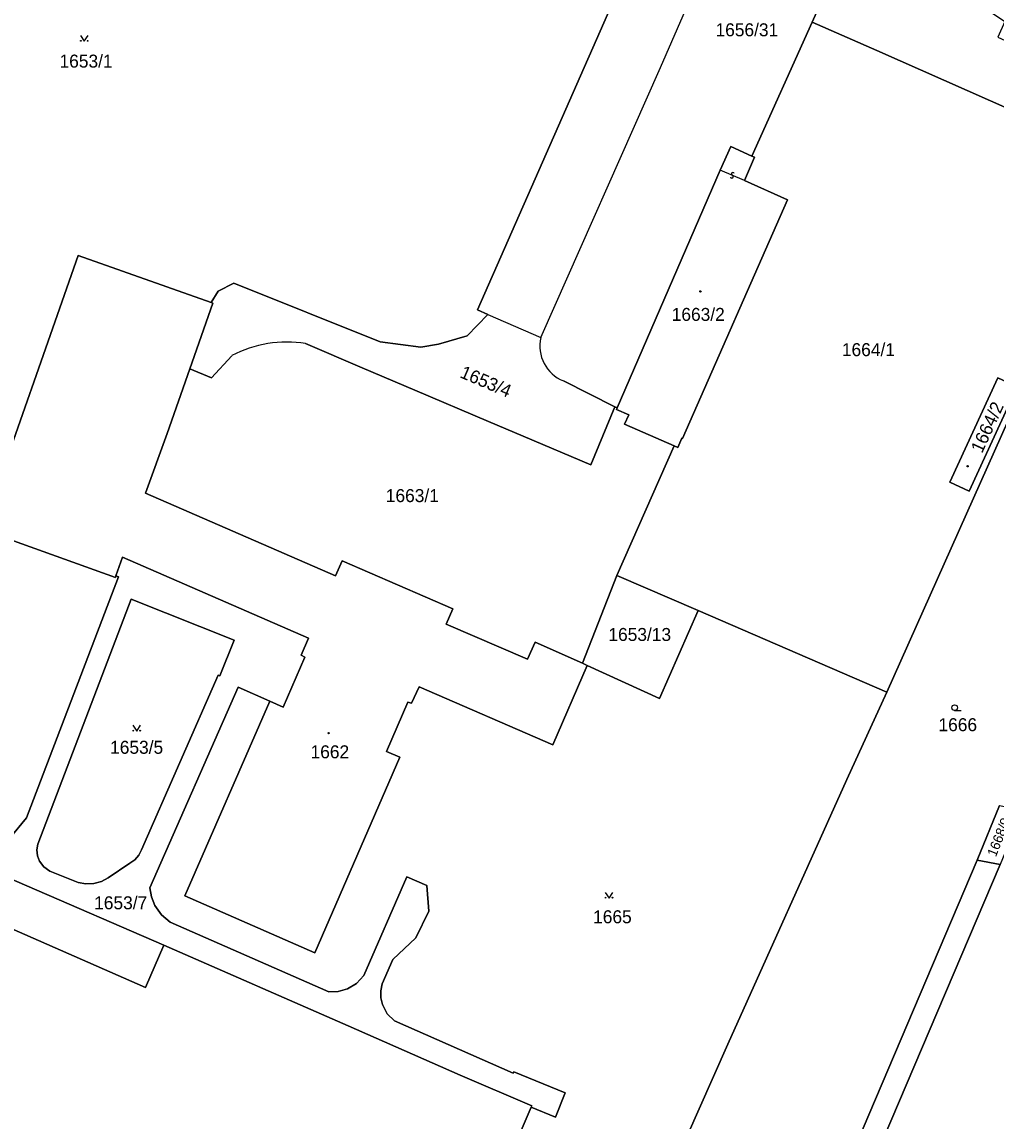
# Model space of a CAD drawing. Extents: x -596024 to -594475, y -1163820 to -1161957.
# Drawn here: x -595823.2 to -595695.5, y -1162318.6 to -1162174.7 of the extents above; entities that cross this region are included whole.
import ezdxf

# ---------------------------------------------------------------- set-up
doc = ezdxf.new("R2010")
doc.units = 0
for name, color, linetype in [('Level 1', 7, 'Continuous'), ('Level 13', 7, 'Continuous'), ('Level 3', 7, 'Continuous'), ('Level 4', 7, 'Continuous'), ('Level 5', 7, 'Continuous'), ('Level 60', 7, 'Continuous'), ('Vrstva 60', 7, 'Continuous')]:
    doc.layers.add(name, color=color, linetype=linetype)

msp = doc.modelspace()

# ---------------------------------------------------------------- linework, layer by layer
at = {"layer": 'Level 1'}
for points in [[(-595762.1, -1162212.98), (-595763.48, -1162212.38), (-595714.28, -1162100.65)], [(-595755.16, -1162216.01), (-595739.48, -1162180.64), (-595719.28, -1162134.23)], [(-595706, -1162144.24), (-595719.62, -1162174.71)], [(-595727.53, -1162192.23), (-595719.62, -1162174.71)], [(-595719.62, -1162174.71), (-595711.16, -1162178.38), (-595678.68, -1162192.78)], [(-595731.66, -1162194.09), (-595730.28, -1162190.99), (-595727.53, -1162192.23)], [(-595728.5, -1162195.42), (-595727.18, -1162192.39), (-595727.53, -1162192.23)], [(-595678.68, -1162192.78), (-595709.83, -1162262.45)], [(-595731.66, -1162194.09), (-595745.18, -1162225.22)], [(-595737.72, -1162230.18), (-595737.2, -1162230.4), (-595736.68, -1162229.18), (-595736.59, -1162229.22), (-595722.85, -1162197.97), (-595728.5, -1162195.42)], [(-595798.39, -1162211.43), (-595815.82, -1162205.27), (-595828.32, -1162240.78)], [(-595762.1, -1162212.98), (-595764.81, -1162215.77), (-595768.57, -1162216.89), (-595770.91, -1162217.26), (-595776.23, -1162216.55), (-595795.42, -1162208.87), (-595797.46, -1162209.91), (-595798.39, -1162211.43)], [(-595798.39, -1162211.43), (-595798.14, -1162211.52), (-595801.17, -1162220.09)], [(-595762.1, -1162212.98), (-595755.16, -1162216.01)], [(-595745.46, -1162225.1), (-595748.64, -1162232.68), (-595757.5, -1162228.92), (-595762.05, -1162226.98), (-595771.67, -1162222.89), (-595778.59, -1162219.96), (-595786, -1162216.78)], [(-595801.17, -1162220.09), (-595798.33, -1162221.3), (-595795.68, -1162218.38)], [(-595801.17, -1162220.09), (-595804.16, -1162228.57), (-595806.98, -1162236.41), (-595795.54, -1162241.38), (-595782.07, -1162247.23), (-595781.19, -1162245.24), (-595766.71, -1162251.52), (-595767.57, -1162253.56), (-595756.9, -1162258.12), (-595755.93, -1162255.92), (-595749.73, -1162258.67)], [(-595745.46, -1162225.1), (-595752.22, -1162221.68)], [(-595699.06, -1162236.11), (-595701.56, -1162234.96), (-595695.28, -1162221.28), (-595692.76, -1162222.44), (-595699.06, -1162236.11)], [(-595745.46, -1162225.1), (-595745.18, -1162225.22)], [(-595745.18, -1162225.22), (-595745.27, -1162225.42), (-595743.65, -1162226.13), (-595744.2, -1162227.37), (-595737.72, -1162230.18)], [(-595737.72, -1162230.18), (-595745.21, -1162247.19)], [(-595810.87, -1162247.24), (-595810.93, -1162247.42), (-595827.12, -1162241.64), (-595828.45, -1162241.16), (-595828.32, -1162240.78)], [(-595790.69, -1162263.65), (-595788.93, -1162264.41), (-595786.12, -1162257.87), (-595786.59, -1162257.63), (-595785.64, -1162255.37), (-595809.99, -1162244.79), (-595810.87, -1162247.24)], [(-595810.87, -1162247.24), (-595810.54, -1162247.36), (-595822.56, -1162278.91), (-595824.79, -1162281.63), (-595825.42, -1162282.16), (-595826.18, -1162282.47), (-595826.9, -1162282.53), (-595827.6, -1162282.39), (-595839.05, -1162277.47), (-595848.14, -1162273.48)], [(-595749.73, -1162258.67), (-595745.21, -1162247.19)], [(-595734.57, -1162251.78), (-595745.21, -1162247.19)], [(-595797.22, -1162260.3), (-595797.46, -1162260.23), (-595807.51, -1162283.11), (-595807.87, -1162283.81), (-595808.38, -1162284.41), (-595809.02, -1162284.87), (-595811.86, -1162286.77), (-595812.76, -1162287.25), (-595813.75, -1162287.52), (-595814.79, -1162287.57), (-595815.82, -1162287.38), (-595819.51, -1162285.89), (-595820.31, -1162285.36), (-595820.89, -1162284.6), (-595821.15, -1162283.89), (-595821.21, -1162283.13), (-595821.08, -1162282.39), (-595808.85, -1162250.28), (-595795.37, -1162255.65), (-595797.22, -1162260.3)], [(-595749.08, -1162258.96), (-595739.6, -1162263.29), (-595734.57, -1162251.78)], [(-595709.83, -1162262.45), (-595734.57, -1162251.78)], [(-595749.08, -1162258.96), (-595753.61, -1162269.36), (-595771.13, -1162261.77), (-595772.12, -1162263.92), (-595772.62, -1162263.76), (-595775.4, -1162270.23), (-595773.63, -1162270.99), (-595784.78, -1162296.59), (-595801.82, -1162289.13), (-595790.69, -1162263.65)], [(-595749.73, -1162258.67), (-595749.08, -1162258.96)], [(-595709.83, -1162262.45), (-595715.05, -1162273.88), (-595730.67, -1162308.59), (-595750.8, -1162353.99), (-595754.29, -1162361.8), (-595797.24, -1162364.8), (-595847.77, -1162368.33)], [(-595756.42, -1162316.82), (-595753.25, -1162318.13), (-595751.97, -1162314.94), (-595758.7, -1162312.19), (-595758.78, -1162312.38), (-595774.35, -1162305.52), (-595775.31, -1162304.58), (-595775.94, -1162303.39), (-595776.15, -1162302.5), (-595776.16, -1162301.58), (-595775.98, -1162300.68), (-595774.56, -1162297.47), (-595771.57, -1162294.66), (-595769.86, -1162291.13), (-595770.13, -1162287.77), (-595772.72, -1162286.67), (-595778.39, -1162299.57), (-595779.33, -1162300.61), (-595780.53, -1162301.34), (-595781.72, -1162301.68), (-595782.96, -1162301.72), (-595803.74, -1162292.6), (-595804.89, -1162291.64), (-595805.75, -1162290.41), (-595806.2, -1162289.28), (-595806.4, -1162288.08), (-595794.86, -1162261.82), (-595790.69, -1162263.65)], [(-595804.6, -1162295.61), (-595840.55, -1162280.07), (-595849.35, -1162276.28)], [(-595695.06, -1162277.29), (-595697.99, -1162284.45)], [(-595697.99, -1162284.45), (-595742.07, -1162388.02)], [(-595742.07, -1162388.02), (-595738.95, -1162388.28), (-595694.97, -1162285.05)], [(-595694.97, -1162285.05), (-595697.99, -1162284.45)], [(-595845.79, -1162320.43), (-595846.57, -1162317.95), (-595847.03, -1162315.39), (-595847.09, -1162313.01), (-595846.88, -1162310.63), (-595846.4, -1162308.3), (-595845.74, -1162306.24), (-595844.87, -1162304.26), (-595837.57, -1162287.72), (-595806.99, -1162301.14), (-595804.6, -1162295.61)], [(-595804.6, -1162295.61), (-595780.44, -1162306.15), (-595765.76, -1162312.62), (-595756.34, -1162316.64), (-595756.42, -1162316.82)], [(-595756.42, -1162316.82), (-595766.21, -1162339.62)]]:
    msp.add_lwpolyline(points, dxfattribs=at)
for centre, radius, start, end in [((-595750.42, -1162217.15), 4.87, 166.4752, 248.34), ((-595788.4, -1162232.32), 15.73, 81.2131, 117.558)]:
    msp.add_arc(centre, radius, start, end, dxfattribs=at)
at = {"layer": 'Level 13'}
for centre, start, end in [((-595730.15, -1162194.92), 194.5472, 66.6452), ((-595730.01, -1162194.58), 14.3327, 246.9227)]:
    msp.add_arc(centre, 0.184, start, end, dxfattribs=at)
at = {"layer": 'Level 3'}
msp.add_lwpolyline([(-595728.5, -1162195.42), (-595731.66, -1162194.09)], dxfattribs=at)
at = {"layer": 'Level 5'}
msp.add_line((-595700.94, -1162264.87), (-595700.07, -1162264.87), dxfattribs=at)
for points in [[(-595815.51, -1162176.44), (-595815.01, -1162177.19), (-595814.51, -1162176.44)], [(-595808.63, -1162266.8), (-595808.13, -1162267.55), (-595807.63, -1162266.8)], [(-595746.73, -1162288.68), (-595746.23, -1162289.43), (-595745.73, -1162288.68)]]:
    msp.add_lwpolyline(points, dxfattribs=at)
for centre, radius in [((-595815.46, -1162177.14), 0.05), ((-595814.56, -1162177.14), 0.05), ((-595734.26, -1162209.96), 0.09), ((-595734.26, -1162209.96), 0.0521), ((-595699.25, -1162232.86), 0.09), ((-595699.25, -1162232.86), 0.0521), ((-595700.94, -1162264.49), 0.375), ((-595808.58, -1162267.5), 0.05), ((-595807.68, -1162267.5), 0.05), ((-595782.98, -1162267.83), 0.09), ((-595782.98, -1162267.83), 0.0521), ((-595746.68, -1162289.38), 0.05), ((-595745.78, -1162289.38), 0.05)]:
    msp.add_circle(centre, radius, dxfattribs=at)
at = {"layer": 'Level 60'}
for points in [[(-595714.28, -1162100.65), (-595763.48, -1162212.38), (-595762.1, -1162212.98), (-595764.81, -1162215.77), (-595768.57, -1162216.89), (-595770.91, -1162217.26), (-595776.23, -1162216.55), (-595795.42, -1162208.87), (-595797.46, -1162209.91), (-595798.39, -1162211.43), (-595815.82, -1162205.27), (-595828.32, -1162240.78), (-595833.81, -1162238.93), (-595849.74, -1162233.3), (-595857.22, -1162230.69), (-595857.76, -1162222.73), (-595860.33, -1162182.22), (-595864.54, -1162120.48)], [(-595755.16, -1162216.01), (-595739.48, -1162180.64), (-595719.28, -1162134.23), (-595719.02, -1162134.18), (-595717.94, -1162134.26), (-595716.63, -1162134.83), (-595709.17, -1162139.04), (-595706.47, -1162142.32), (-595706, -1162144.24), (-595719.62, -1162174.71), (-595727.53, -1162192.23), (-595730.28, -1162190.99), (-595731.66, -1162194.09), (-595745.18, -1162225.22), (-595745.46, -1162225.1), (-595752.22, -1162221.68)], [(-595695.06, -1162277.29), (-595697.99, -1162284.45), (-595742.07, -1162388.02), (-595765.12, -1162385.49), (-595781.67, -1162383.67), (-595847.7, -1162376.42), (-595848.22, -1162368.36), (-595847.77, -1162368.33), (-595797.24, -1162364.8), (-595754.29, -1162361.8), (-595750.8, -1162353.99), (-595730.67, -1162308.59), (-595715.05, -1162273.88), (-595709.83, -1162262.45), (-595678.68, -1162192.78)], [(-595828.32, -1162240.78), (-595815.82, -1162205.27), (-595798.39, -1162211.43), (-595798.14, -1162211.52), (-595801.17, -1162220.09), (-595804.16, -1162228.57), (-595806.98, -1162236.41), (-595795.54, -1162241.38), (-595782.07, -1162247.23), (-595781.19, -1162245.24), (-595766.71, -1162251.52), (-595767.57, -1162253.56), (-595756.9, -1162258.12), (-595755.93, -1162255.92), (-595749.73, -1162258.67), (-595749.08, -1162258.96), (-595753.61, -1162269.36), (-595771.13, -1162261.77), (-595772.12, -1162263.92), (-595772.62, -1162263.76), (-595775.4, -1162270.23), (-595773.63, -1162270.99), (-595784.78, -1162296.59), (-595801.82, -1162289.13), (-595790.69, -1162263.65), (-595788.93, -1162264.41), (-595786.12, -1162257.87), (-595786.59, -1162257.63), (-595785.64, -1162255.37), (-595809.99, -1162244.79), (-595810.87, -1162247.24), (-595810.93, -1162247.42), (-595827.12, -1162241.64)], [(-595795.68, -1162218.38), (-595798.33, -1162221.3), (-595801.17, -1162220.09), (-595798.14, -1162211.52), (-595798.39, -1162211.43), (-595797.46, -1162209.91), (-595795.42, -1162208.87), (-595776.23, -1162216.55), (-595770.91, -1162217.26), (-595768.57, -1162216.89), (-595764.81, -1162215.77), (-595762.1, -1162212.98), (-595755.16, -1162216.01)], [(-595786, -1162216.78), (-595778.59, -1162219.96), (-595771.67, -1162222.89), (-595762.05, -1162226.98), (-595757.5, -1162228.92), (-595748.64, -1162232.68), (-595745.46, -1162225.1), (-595745.18, -1162225.22), (-595745.27, -1162225.42), (-595743.65, -1162226.13), (-595744.2, -1162227.37), (-595737.72, -1162230.18), (-595745.21, -1162247.19), (-595749.73, -1162258.67), (-595755.93, -1162255.92), (-595756.9, -1162258.12), (-595767.57, -1162253.56), (-595766.71, -1162251.52), (-595781.19, -1162245.24), (-595782.07, -1162247.23), (-595795.54, -1162241.38), (-595806.98, -1162236.41), (-595804.16, -1162228.57)], [(-595752.22, -1162221.68), (-595745.46, -1162225.1), (-595748.64, -1162232.68), (-595757.5, -1162228.92), (-595762.05, -1162226.98), (-595771.67, -1162222.89), (-595778.59, -1162219.96), (-595786, -1162216.78)], [(-595804.16, -1162228.57), (-595801.17, -1162220.09), (-595798.33, -1162221.3), (-595795.68, -1162218.38)], [(-595824.79, -1162281.63), (-595822.56, -1162278.91), (-595810.54, -1162247.36), (-595810.87, -1162247.24), (-595809.99, -1162244.79), (-595785.64, -1162255.37), (-595786.59, -1162257.63), (-595786.12, -1162257.87), (-595788.93, -1162264.41), (-595790.69, -1162263.65), (-595794.86, -1162261.82), (-595806.4, -1162288.08), (-595806.2, -1162289.28), (-595805.75, -1162290.41), (-595804.89, -1162291.64), (-595803.74, -1162292.6), (-595782.96, -1162301.72), (-595781.72, -1162301.68), (-595780.53, -1162301.34), (-595779.33, -1162300.61), (-595778.39, -1162299.57), (-595772.72, -1162286.67), (-595770.13, -1162287.77), (-595769.86, -1162291.13), (-595771.57, -1162294.66), (-595774.56, -1162297.47), (-595775.98, -1162300.68), (-595776.16, -1162301.58), (-595776.15, -1162302.5), (-595775.94, -1162303.39), (-595775.31, -1162304.58), (-595774.35, -1162305.52), (-595758.78, -1162312.38), (-595758.7, -1162312.19), (-595751.97, -1162314.94), (-595753.25, -1162318.13), (-595756.42, -1162316.82), (-595756.34, -1162316.64), (-595765.76, -1162312.62), (-595780.44, -1162306.15), (-595804.6, -1162295.61), (-595840.55, -1162280.07)], [(-595766.21, -1162339.62), (-595756.42, -1162316.82), (-595753.25, -1162318.13), (-595751.97, -1162314.94), (-595758.7, -1162312.19), (-595758.78, -1162312.38), (-595774.35, -1162305.52), (-595775.31, -1162304.58), (-595775.94, -1162303.39), (-595776.15, -1162302.5), (-595776.16, -1162301.58), (-595775.98, -1162300.68), (-595774.56, -1162297.47), (-595771.57, -1162294.66), (-595769.86, -1162291.13), (-595770.13, -1162287.77), (-595772.72, -1162286.67), (-595778.39, -1162299.57), (-595779.33, -1162300.61), (-595780.53, -1162301.34), (-595781.72, -1162301.68), (-595782.96, -1162301.72), (-595803.74, -1162292.6), (-595804.89, -1162291.64), (-595805.75, -1162290.41), (-595806.2, -1162289.28), (-595806.4, -1162288.08), (-595794.86, -1162261.82), (-595790.69, -1162263.65), (-595801.82, -1162289.13), (-595784.78, -1162296.59), (-595773.63, -1162270.99), (-595775.4, -1162270.23), (-595772.62, -1162263.76), (-595772.12, -1162263.92), (-595771.13, -1162261.77), (-595753.61, -1162269.36), (-595749.08, -1162258.96), (-595739.6, -1162263.29), (-595734.57, -1162251.78), (-595709.83, -1162262.45), (-595715.05, -1162273.88)], [(-595715.05, -1162273.88), (-595730.67, -1162308.59), (-595750.8, -1162353.99)], [(-595848.46, -1162342.58), (-595849.42, -1162310.72), (-595849.67, -1162295.34), (-595849.38, -1162294.6), (-595844.56, -1162283.08), (-595845.61, -1162282.29), (-595853.94, -1162279.72), (-595853.95, -1162279.53), (-595849.62, -1162276.89), (-595849.35, -1162276.28), (-595840.55, -1162280.07), (-595804.6, -1162295.61), (-595806.99, -1162301.14), (-595837.57, -1162287.72), (-595844.87, -1162304.26), (-595845.74, -1162306.24), (-595846.4, -1162308.3), (-595846.88, -1162310.63), (-595847.09, -1162313.01), (-595847.03, -1162315.39), (-595846.57, -1162317.95), (-595845.79, -1162320.43)], [(-595781.32, -1162422.62), (-595742.07, -1162388.02), (-595738.95, -1162388.28), (-595694.97, -1162285.05)], [(-595845.79, -1162320.43), (-595846.57, -1162317.95), (-595847.03, -1162315.39), (-595847.09, -1162313.01), (-595846.88, -1162310.63), (-595846.4, -1162308.3), (-595845.74, -1162306.24), (-595844.87, -1162304.26), (-595837.57, -1162287.72), (-595806.99, -1162301.14), (-595804.6, -1162295.61), (-595780.44, -1162306.15), (-595765.76, -1162312.62), (-595756.34, -1162316.64), (-595756.42, -1162316.82), (-595766.21, -1162339.62)]]:
    msp.add_lwpolyline(points, dxfattribs=at)
for points in [[(-595676.18, -1162186.39), (-595678.68, -1162192.78), (-595711.16, -1162178.38), (-595719.62, -1162174.71), (-595706, -1162144.24), (-595705.65, -1162145.68), (-595706.74, -1162150.45), (-595709, -1162156.03), (-595709.47, -1162159.02), (-595708.67, -1162162.88), (-595705.41, -1162167.16), (-595694.35, -1162174.62), (-595695.27, -1162176.64), (-595684.44, -1162181.57), (-595684.84, -1162182.49), (-595680.04, -1162184.66)], [(-595737.72, -1162230.18), (-595737.2, -1162230.4), (-595736.68, -1162229.18), (-595736.59, -1162229.22), (-595722.85, -1162197.97), (-595728.5, -1162195.42), (-595727.18, -1162192.39), (-595727.53, -1162192.23), (-595719.62, -1162174.71), (-595711.16, -1162178.38), (-595678.68, -1162192.78), (-595709.83, -1162262.45), (-595734.57, -1162251.78), (-595745.21, -1162247.19)], [(-595743.65, -1162226.13), (-595745.27, -1162225.42), (-595745.18, -1162225.22), (-595731.66, -1162194.09), (-595730.28, -1162190.99), (-595727.53, -1162192.23), (-595727.18, -1162192.39), (-595728.5, -1162195.42), (-595722.85, -1162197.97), (-595736.59, -1162229.22), (-595736.68, -1162229.18), (-595737.2, -1162230.4), (-595737.72, -1162230.18), (-595744.2, -1162227.37)], [(-595701.56, -1162234.96), (-595699.06, -1162236.11), (-595692.76, -1162222.44), (-595695.28, -1162221.28)], [(-595699.06, -1162236.11), (-595701.56, -1162234.96), (-595695.28, -1162221.28), (-595692.76, -1162222.44)], [(-595827.12, -1162241.64), (-595810.93, -1162247.42), (-595810.87, -1162247.24), (-595810.54, -1162247.36), (-595822.56, -1162278.91), (-595824.79, -1162281.63), (-595825.42, -1162282.16), (-595826.18, -1162282.47), (-595826.9, -1162282.53), (-595827.6, -1162282.39), (-595839.05, -1162277.47), (-595848.14, -1162273.48), (-595847.95, -1162273.04), (-595850.89, -1162270.88), (-595853.15, -1162268.79), (-595851.44, -1162251.11), (-595849.74, -1162233.3), (-595833.81, -1162238.93), (-595828.32, -1162240.78), (-595828.45, -1162241.16)], [(-595739.6, -1162263.29), (-595749.08, -1162258.96), (-595749.73, -1162258.67), (-595745.21, -1162247.19), (-595734.57, -1162251.78)], [(-595797.22, -1162260.3), (-595797.46, -1162260.23), (-595807.51, -1162283.11), (-595807.87, -1162283.81), (-595808.38, -1162284.41), (-595809.02, -1162284.87), (-595811.86, -1162286.77), (-595812.76, -1162287.25), (-595813.75, -1162287.52), (-595814.79, -1162287.57), (-595815.82, -1162287.38), (-595819.51, -1162285.89), (-595820.31, -1162285.36), (-595820.89, -1162284.6), (-595821.15, -1162283.89), (-595821.21, -1162283.13), (-595821.08, -1162282.39), (-595808.85, -1162250.28), (-595795.37, -1162255.65)], [(-595797.46, -1162260.23), (-595797.22, -1162260.3), (-595795.37, -1162255.65), (-595808.85, -1162250.28), (-595821.08, -1162282.39), (-595821.21, -1162283.13), (-595821.15, -1162283.89), (-595820.89, -1162284.6), (-595820.31, -1162285.36), (-595819.51, -1162285.89), (-595815.82, -1162287.38), (-595814.79, -1162287.57), (-595813.75, -1162287.52), (-595812.76, -1162287.25), (-595811.86, -1162286.77), (-595809.02, -1162284.87), (-595808.38, -1162284.41), (-595807.87, -1162283.81), (-595807.51, -1162283.11)], [(-595695.06, -1162277.29), (-595692.05, -1162277.92), (-595694.97, -1162285.05), (-595697.99, -1162284.45)], [(-595738.95, -1162388.28), (-595742.07, -1162388.02), (-595697.99, -1162284.45), (-595694.97, -1162285.05)]]:
    msp.add_lwpolyline(points, close=True, dxfattribs=at)
for centre, radius, start, end in [((-595750.42, -1162217.15), 4.87, 166.4752, 248.34), ((-595750.42, -1162217.15), 4.87, 166.4752, 248.34), ((-595788.4, -1162232.32), 15.73, 81.2131, 117.558), ((-595788.4, -1162232.32), 15.73, 81.2131, 117.558)]:
    msp.add_arc(centre, radius, start, end, dxfattribs=at)
at = {"layer": 'Vrstva 60'}
msp.add_lwpolyline([(-595642.93, -1161956.88), (-595651.68, -1161956.88), (-595700.42, -1162067.92), (-595714.28, -1162100.65), (-595763.48, -1162212.38), (-595762.1, -1162212.98), (-595755.16, -1162216.01), (-595739.48, -1162180.64), (-595719.28, -1162134.23), (-595717.11, -1162129.24), (-595707.38, -1162106.85), (-595708.77, -1162106.24), (-595707.38, -1162103.08), (-595698.23, -1162081.48), (-595688.29, -1162059.74), (-595682.95, -1162047.47), (-595655.76, -1161985.63), (-595650.46, -1161973.92)], close=True, dxfattribs=at)

# ---------------------------------------------------------------- texts
at = {"layer": 'Level 4'}
for s, p in [('1656/31', (-595732.28, -1162176.54)), ('1653/1', (-595818.25, -1162180.64)), ('1663/2', (-595738.02, -1162213.82)), ('1664/1', (-595715.72, -1162218.44)), ('1663/1', (-595775.49, -1162237.56)), ('1653/13', (-595746.32, -1162255.75)), ('1666', (-595703.06, -1162267.57)), ('1653/5', (-595811.62, -1162270.53)), ('1662', (-595785.35, -1162271.12)), ('1653/7', (-595813.71, -1162290.9)), ('1665', (-595748.32, -1162292.73))]:
    msp.add_text(s, height=1.7, dxfattribs=at).set_placement(p)
for s, height, rotation, p in [('1653/4', 1.7, 336.9698, (-595765.9, -1162221.18)), ('1664/2', 1.7, 65.3418, (-595697.35, -1162231.25)), ('1668/9', 1.28, 68.2041, (-595695.54, -1162284.11))]:
    msp.add_text(s, height=height, rotation=rotation, dxfattribs=at).set_placement(p)

doc.saveas('drawing.dxf')
